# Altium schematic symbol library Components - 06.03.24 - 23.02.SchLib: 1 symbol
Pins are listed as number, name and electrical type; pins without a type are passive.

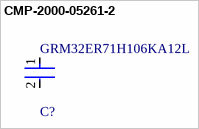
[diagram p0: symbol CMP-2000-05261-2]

## CMP-2000-05261-2
designator C?, comment GRM32ER71H106KA12L
CAP CER 10UF 50V X7R 1210; Manufacturer: Murata; Tolerance: 10%; Material: Ceramic; Temperature Coefficient: 15%
footprint FP-GRM32-IPC_A
footprint FP-GRM32-MFG
footprint FP-GRM32-IPC_C
footprint FP-GRM32-IPC_B
pins: 1, 2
